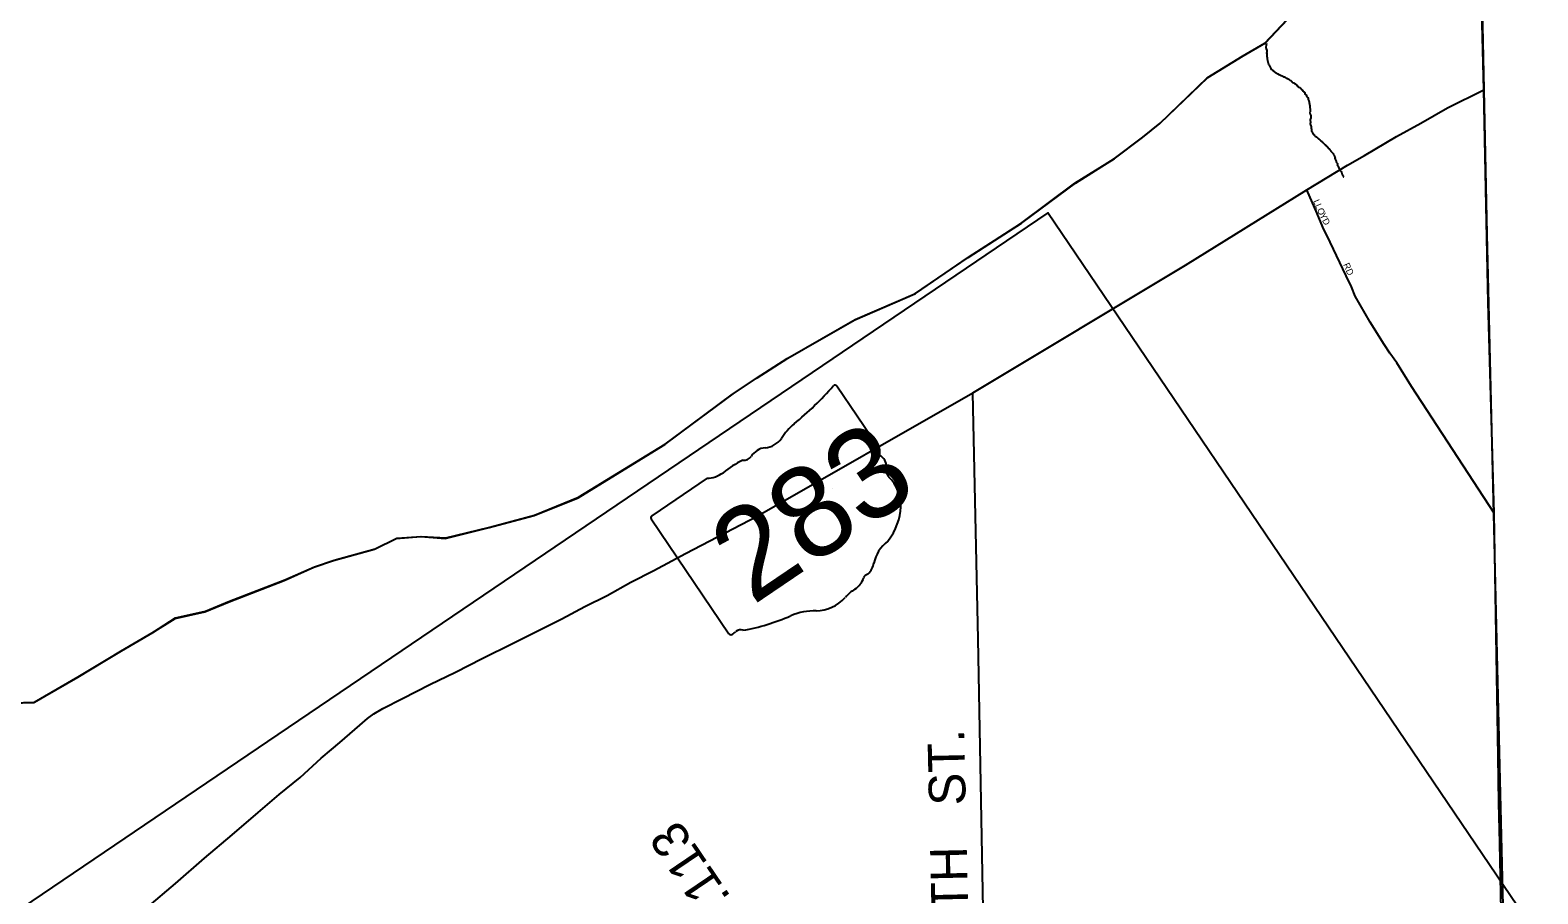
# Model space of a CAD drawing. Extents: x 2139079 to 2262683, y 1235796 to 1334992.
# Drawn here: x 2234072 to 2245568, y 1316743 to 1323327 of the extents above; entities that cross this region are included whole.
import ezdxf

# ---------------------------------------------------------------- set-up
doc = ezdxf.new("R2010")
doc.units = 0
for name, color, linetype in [('Default', 7, 'Continuous'), ('GM_X_Adjacent_County', 7, 'Continuous'), ('GM_X_City_Street', 7, 'Continuous'), ('GM_X_City_Street_Text', 7, 'Continuous'), ('GM_X_Interchange_Ramps', 7, 'Continuous'), ('GM_X_Interstate_Route', 7, 'Continuous'), ('GM_X_Major_Lake', 7, 'Continuous'), ('GM_X_Minor_River', 7, 'Continuous'), ('GM_X_State_Location', 7, 'Continuous'), ('GM_X_State_Route', 7, 'Continuous'), ('GM_X_State_Shield', 7, 'Continuous'), ('GM_X_US_Route', 7, 'Continuous')]:
    doc.layers.add(name, color=color, linetype=linetype)

msp = doc.modelspace()

# ---------------------------------------------------------------- linework, layer by layer
at = {"layer": 'GM_X_Adjacent_County'}
msp.add_lwpolyline([(2245541, 1302192), (2245528, 1304087), (2245507, 1306573), (2245466, 1311124), (2245451, 1311744), (2245406, 1312275), (2245366, 1313013), (2245298, 1316197), (2245294, 1316360), (2245278, 1317130), (2245271, 1317437), (2245264, 1317789), (2245234, 1319644), (2245190, 1321250), (2245174, 1321990), (2245155, 1322872), (2245144, 1323376), (2245140, 1323785), (2245134, 1324581), (2245318, 1324775), (2245503, 1324980), (2245556, 1325020), (2245646, 1325055)], dxfattribs=at)
at = {"layer": 'GM_X_City_Street'}
msp.add_lwpolyline([(2245234, 1319644), (2244605, 1320610), (2244492, 1320790), (2244439, 1320864), (2244395, 1320932), (2244288, 1321100), (2244174, 1321299), (2244146, 1321370), (2244107, 1321455), (2243985, 1321712), (2243929, 1321826), (2243886, 1321930), (2243805, 1322111)], dxfattribs=at)
at = {"layer": 'GM_X_Interstate_Route'}
for points in [[(2233929, 1318196), (2234100, 1318202), (2234435, 1318394), (2234764, 1318592), (2235003, 1318733), (2235177, 1318843), (2235405, 1318894), (2235589, 1318970), (2236008, 1319133), (2236236, 1319234), (2236386, 1319284), (2236698, 1319371), (2236864, 1319451), (2237051, 1319466), (2237237, 1319453), (2237572, 1319535), (2237914, 1319627), (2238250, 1319763), (2238910, 1320168), (2239427, 1320552), (2239611, 1320675), (2239844, 1320824), (2240359, 1321118), (2240818, 1321318), (2241223, 1321593), (2241625, 1321854), (2242037, 1322160), (2242336, 1322347), (2242552, 1322509), (2242685, 1322616), (2243047, 1322964), (2243317, 1323129), (2243486, 1323228), (2243654, 1323405)], [(2233929, 1318196), (2234100, 1318202), (2234435, 1318394), (2234764, 1318592), (2235003, 1318733), (2235177, 1318843), (2235405, 1318894), (2235589, 1318970), (2236008, 1319133), (2236236, 1319234), (2236386, 1319284), (2236698, 1319371), (2236864, 1319451), (2237051, 1319466), (2237237, 1319453), (2237572, 1319535), (2237914, 1319627), (2238250, 1319763), (2238910, 1320168), (2239427, 1320552), (2239611, 1320675), (2239844, 1320824), (2240359, 1321118), (2240818, 1321318), (2241223, 1321593), (2241625, 1321854), (2242037, 1322160), (2242336, 1322347), (2242552, 1322509), (2242685, 1322616), (2243047, 1322964), (2243317, 1323129), (2243486, 1323228), (2243654, 1323405)], [(2245142, 1323484), (2245178, 1321773), (2245406, 1312275), (2245451, 1311744), (2245466, 1311124), (2245458, 1308807), (2245473, 1308109), (2243489, 1308053), (2243515, 1306895), (2242283, 1306903), (2241498, 1306888), (2241571, 1303589)], [(2245142, 1323484), (2245178, 1321773), (2245406, 1312275), (2245451, 1311744), (2245466, 1311124), (2245458, 1308807), (2245473, 1308109), (2243489, 1308053), (2243515, 1306895), (2242283, 1306903), (2241498, 1306888), (2241571, 1303589)]]:
    msp.add_lwpolyline(points, dxfattribs=at)
at = {"layer": 'GM_X_Major_Lake'}
for points in [[(2242042, 1322162), (2242340, 1322350), (2242557, 1322512), (2242689, 1322618), (2243051, 1322967), (2243321, 1323132), (2243490, 1323231), (2243658, 1323408), (2244029, 1323665), (2244434, 1323992), (2244610, 1324143), (2244832, 1324328), (2245018, 1324487), (2245138, 1324583)], [(2233934, 1318199), (2234104, 1318204), (2234439, 1318397), (2234768, 1318595), (2235008, 1318736), (2235181, 1318846), (2235409, 1318897), (2235593, 1318973), (2236013, 1319136), (2236241, 1319237), (2236391, 1319286), (2236703, 1319374), (2236869, 1319454), (2237055, 1319468), (2237242, 1319456), (2237576, 1319538), (2237918, 1319630), (2238254, 1319766), (2238914, 1320170), (2239432, 1320555), (2239615, 1320677), (2239848, 1320826), (2240363, 1321121), (2240823, 1321320), (2241227, 1321596), (2241630, 1321857), (2242042, 1322162)]]:
    msp.add_lwpolyline(points, dxfattribs=at)
at = {"layer": 'GM_X_Minor_River'}
for points in [[(2243499, 1323226), (2243500, 1323172), (2243502, 1323168), (2243502, 1323166), (2243500, 1323160), (2243500, 1323148), (2243502, 1323142), (2243502, 1323124), (2243504, 1323116), (2243504, 1323108), (2243506, 1323100), (2243506, 1323094), (2243508, 1323088), (2243510, 1323080), (2243512, 1323074), (2243514, 1323066), (2243518, 1323060), (2243523, 1323050), (2243529, 1323040), (2243533, 1323034), (2243545, 1323022), (2243551, 1323018), (2243551, 1323016), (2243561, 1323008), (2243567, 1323004), (2243569, 1323002), (2243573, 1323002), (2243577, 1322996), (2243581, 1322996), (2243587, 1322994), (2243591, 1322990), (2243595, 1322988), (2243605, 1322984), (2243617, 1322980), (2243629, 1322972), (2243641, 1322968), (2243645, 1322964), (2243649, 1322962), (2243659, 1322958), (2243677, 1322947), (2243680, 1322945), (2243684, 1322943), (2243690, 1322939), (2243692, 1322933), (2243708, 1322925), (2243714, 1322921), (2243714, 1322919), (2243720, 1322917), (2243724, 1322913), (2243732, 1322905), (2243736, 1322903), (2243738, 1322899), (2243744, 1322893), (2243750, 1322891), (2243756, 1322887), (2243760, 1322881), (2243766, 1322875), (2243770, 1322873), (2243772, 1322869), (2243784, 1322857), (2243790, 1322851), (2243792, 1322843), (2243800, 1322835), (2243809, 1322819), (2243813, 1322813), (2243817, 1322797), (2243821, 1322789), (2243823, 1322781), (2243823, 1322775), (2243827, 1322767), (2243827, 1322759), (2243829, 1322745), (2243829, 1322735), (2243831, 1322729), (2243832, 1322687), (2243834, 1322683), (2243834, 1322651), (2243832, 1322639), (2243832, 1322633), (2243834, 1322627), (2243832, 1322619), (2243832, 1322611), (2243836, 1322599), (2243839, 1322587), (2243839, 1322579), (2243841, 1322575), (2243841, 1322565), (2243843, 1322557), (2243847, 1322549), (2243853, 1322539), (2243857, 1322533), (2243861, 1322531), (2243863, 1322527), (2243871, 1322519), (2243879, 1322515), (2243887, 1322507), (2243891, 1322505)], [(2243891, 1322505), (2243893, 1322501), (2243899, 1322497), (2243913, 1322484), (2243922, 1322478), (2243926, 1322472), (2243932, 1322468), (2243936, 1322462), (2243944, 1322456), (2243952, 1322448), (2243958, 1322444), (2243960, 1322440), (2243964, 1322438), (2243966, 1322432), (2243972, 1322426), (2243978, 1322422), (2243982, 1322416), (2243988, 1322408), (2243992, 1322402), (2244002, 1322392), (2244006, 1322388), (2244008, 1322386), (2244010, 1322382), (2244012, 1322374), (2244016, 1322370), (2244016, 1322368), (2244021, 1322360), (2244021, 1322352), (2244027, 1322334), (2244029, 1322330), (2244031, 1322322), (2244039, 1322310), (2244039, 1322304), (2244039, 1322296), (2244047, 1322288), (2244047, 1322280), (2244049, 1322280), (2244051, 1322274), (2244055, 1322270), (2244055, 1322268), (2244059, 1322260), (2244063, 1322254), (2244070, 1322244), (2244072, 1322236), (2244076, 1322230), (2244078, 1322222), (2244082, 1322218), (2244084, 1322214), (2244086, 1322208), (2244088, 1322210)]]:
    msp.add_spline(points, degree=3, dxfattribs=at)
at = {"layer": 'GM_X_State_Route'}
for points in [[(2241260, 1320563), (2241260, 1320563), (2242880, 1321536), (2243805, 1322111), (2244116, 1322297), (2244247, 1322373), (2244491, 1322517), (2244675, 1322617), (2244879, 1322734), (2245155, 1322872)], [(2236370, 1317843), (2236434, 1317898), (2236585, 1318028), (2236645, 1318080), (2236693, 1318115), (2236761, 1318155), (2236912, 1318233), (2237120, 1318340), (2237314, 1318434), (2237519, 1318538), (2237755, 1318654), (2237963, 1318758), (2238126, 1318839), (2238300, 1318933), (2238472, 1319018), (2238651, 1319118), (2238827, 1319207), (2239068, 1319338), (2239616, 1319623), (2241260, 1320563)], [(2241391, 1313507), (2241390, 1313558), (2241391, 1313747), (2241301, 1318685), (2241260, 1320563)], [(2233896, 1315721), (2234781, 1316477), (2234965, 1316640), (2235180, 1316822), (2235401, 1317014), (2235612, 1317192), (2235811, 1317362), (2235970, 1317500), (2236130, 1317631), (2236291, 1317777), (2236370, 1317843)]]:
    msp.add_lwpolyline(points, dxfattribs=at)
at = {"layer": 'GM_X_State_Shield'}
for p, q in [((2240533, 1320156), (2240223, 1320614)), ((2240533, 1320156), (2240533, 1320156)), ((2239233, 1319912), (2238811, 1319626)), ((2238807, 1319601), (2239400, 1318726))]:
    msp.add_line(p, q, dxfattribs=at)
for centre, major_axis, start_param, end_param in [((2240206, 1320605), (16, 10.9), 6.141152, 7.989035), ((2238917, 1321437), (1528, 1035), 4.814394, 5.042369), ((2240101, 1320109), (307, 208), 1.699011, 2.107814), ((2239694, 1320266), (117, 79), 4.081561, 5.145723), ((2239720, 1319525), (581, 394), 1.404758, 1.657858), ((2239525, 1320097), (46.7, 31.6), 3.836095, 5.185415), ((2239662, 1320042), (97.1, 65.8), 0.950623, 2.079405), ((2240552, 1320120), (24.8, 16.8), 1.883978, 3.671073), ((2240517, 1320143), (17.2, 11.6), 5.05454, 6.418171), ((2240434, 1319955), (149, 101), 5.934695, 6.695948), ((2239265, 1320081), (162, 110), 4.042523, 4.731795), ((2240720, 1320004), (108, 73), 2.387724, 3.262537), ((2240275, 1319617), (382, 259), 5.101752, 6.440018), ((2238823, 1319614), (16.7, 11.3), 1.712693, 3.28349), ((2240741, 1319276), (209, 142), 1.647645, 2.488434), ((2240367, 1319257), (123, 84), 4.937069, 5.64225), ((2240299, 1319160), (117, 79), 4.691044, 5.507374), ((2240462, 1319147), (32.9, 22.3), 1.147584, 2.315152), ((2240444, 1318912), (180, 122), 1.495662, 1.94098), ((2239968, 1318538), (345, 234), 0.823519, 1.323587), ((2240112, 1319129), (219, 148), 4.026481, 4.996735), ((2239532, 1319889), (1103, 747), 4.195997, 4.488961), ((2239418, 1318736), (16.8, 11.4), 3.00124, 4.508301), ((2239360, 1318827), (129, 87), 4.665946, 4.897461), ((2239480, 1318707), (46.3, 31.4), 0.519207, 1.627899)]:
    msp.add_ellipse(centre, major_axis=major_axis, ratio=0.8, start_param=start_param, end_param=end_param, dxfattribs=at)
at = {"layer": 'GM_X_US_Route'}
msp.add_lwpolyline([(2202868, 1295541), (2210354, 1284489), (2249318, 1310882), (2241832, 1321934)], close=True, dxfattribs=at)

# ---------------------------------------------------------------- texts
at = {"layer": 'Default'}
msp.add_text('CUY-90-29.113', height=280, rotation=124.1113, dxfattribs=at).set_placement((2240471, 1315165))
at = {"layer": 'GM_X_City_Street_Text'}
for s, rotation, p in [('L', 293.2524, (2243853, 1322024)), ('L', 293.2676, (2243867, 1321992)), ('O', 294.863, (2243882, 1321958)), ('Y', 297.4116, (2243901, 1321916)), ('D', 297.5471, (2243921, 1321877)), ('RD', 293.9591, (2244082, 1321540))]:
    msp.add_text(s, height=50, rotation=rotation, dxfattribs=at).set_placement(p)
at = {"layer": 'GM_X_Interchange_Ramps'}
msp.add_text('E.   260TH   ST.', height=280, rotation=91.3108, dxfattribs=at).set_placement((2241254, 1315318))
at = {"layer": 'GM_X_State_Location'}
for s in ['s', 'r']:
    msp.add_text(s, height=1, dxfattribs=at).set_placement((2240189, 1319833))
msp.add_text('283', height=1, rotation=0, dxfattribs=at).set_placement((2239836, 1319760))
at = {"layer": 'GM_X_State_Shield'}
msp.add_text('283', height=696.1, rotation=34.1114, dxfattribs=at).set_placement((2239580, 1318938))

doc.saveas('drawing.dxf')
